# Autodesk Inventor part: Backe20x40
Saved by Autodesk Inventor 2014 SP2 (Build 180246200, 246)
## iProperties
Created: 2015-06
Part Number: Backe20x40
Material: Generisch
Document SubType Name: Modeling
Designer: e_krauts
Density: 1 g/cm^3
Appearance: Vorgabe
Mass: 248.162 g
Surface Area: 424.262 cm^2
Volume: 248.162 cm^3
Sending System: SolidWorks 2011
Last Author: e_boekem
Author: e_krauts
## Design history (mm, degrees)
node "Backe20x40.ipt1"
node "Aufsatz-Linear austragen5"
node "Basis1"
